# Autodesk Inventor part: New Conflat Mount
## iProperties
Shininess: 64.0
Length Units: 11272
Angle Units: 11279
Time Units: 11290
Mass Units: 11286
Length Display Precision: 3
Angle Display Precision: 2
Compacted: True
Part Number: New Conflat Mount
Document SubType Name: Modeling
Created: 2003-08
Designer: FT User
Manufacturer: Standard
Standards Organization: Custom
Density: 0.0
Volumn: 0.0
Area: 0.0
PropertySet Name: Model Information
Control State: 0
Master: False
Checked Out: False
Author: FT User
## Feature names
1. Revolution1
2. Flange Holes [Hole]
3. Center Hole [Extrusion]
4. Blade Recess [Extrusion]
5. O-ring Groove [Extrusion]
6. xPole Macor Recess [Extrusion]
7. Thread Plate Mount [Extrusion]
8. Rod Hole [Hole]
9. Fillet3
10. Rod O-ring Hole [Hole]
11. Hole5
12. Chamfer1
